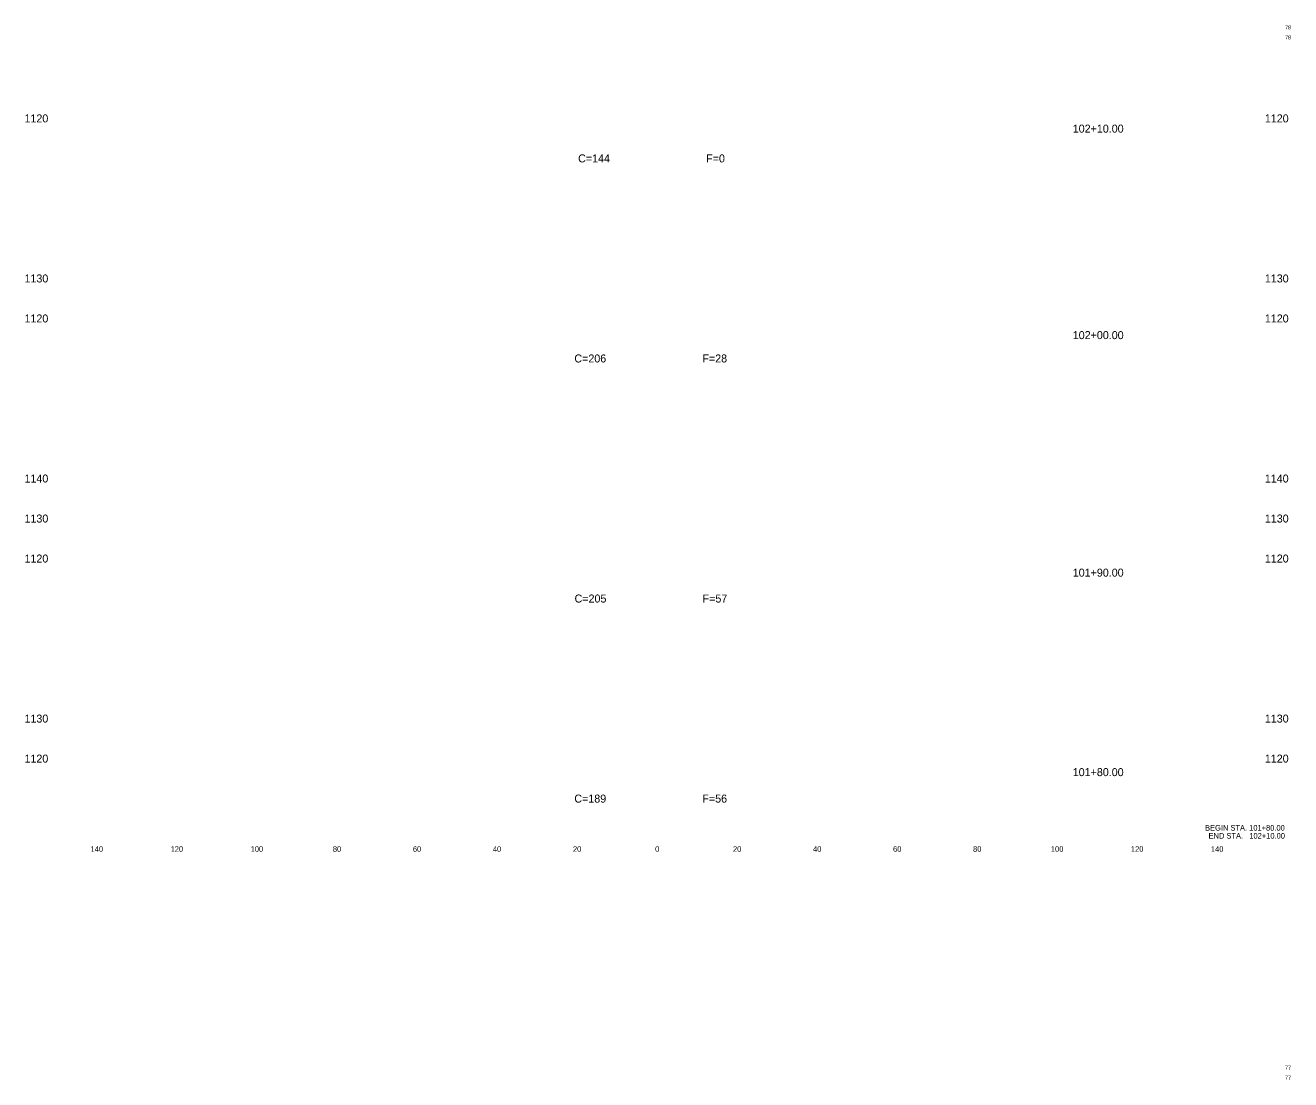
# Model space of a CAD drawing. Extents: x -200 to 1318, y -200 to 2244.
# Drawn here: x 1001.9 to 1318.2, y 1980.8 to 2244.3 of the extents above; entities that cross this region are included whole.
import ezdxf

# ---------------------------------------------------------------- set-up
doc = ezdxf.new("R2010")
doc.units = 0
for name, color, linetype in [('Default', 7, 'Continuous'), ('DESIGN - SHEET - Corner Text', 7, 'Continuous'), ('DESIGN - TYPICAL - Text', 7, 'Continuous')]:
    doc.layers.add(name, color=color, linetype=linetype)

msp = doc.modelspace()

# ---------------------------------------------------------------- texts
at = {"layer": 'Default'}
for s, height, p in [('     1120     ', 2, (998.01, 2220)), ('     1120     ', 2, (1308.01, 2220)), ('     102+10.00     ', 2, (1260, 2217.44)), ('     1130     ', 2, (998.01, 2180)), ('     1130     ', 2, (1308.01, 2180)), ('     1120     ', 2, (998.01, 2170)), ('     1120     ', 2, (1308.01, 2170)), ('     102+00.00     ', 2, (1260, 2165.84)), ('     1140     ', 2, (998.01, 2130)), ('     1140     ', 2, (1308.01, 2130)), ('     1130     ', 2, (998.01, 2120)), ('     1130     ', 2, (1308.01, 2120)), ('     1120     ', 2, (998.01, 2110)), ('     1120     ', 2, (1308.01, 2110)), ('     101+90.00     ', 2, (1260, 2106.47)), ('     1130     ', 2, (998.01, 2070)), ('     1130     ', 2, (1308.01, 2070)), ('     1120     ', 2, (998.01, 2060)), ('     1120     ', 2, (1308.01, 2060)), ('     101+80.00     ', 2, (1260, 2056.62)), ('     140     ', 1.4, (1015.65, 2037.7)), ('     120     ', 1.4, (1035.65, 2037.7)), ('     100     ', 1.4, (1055.65, 2037.7)), ('     80     ', 1.4, (1076.2, 2037.7)), ('     60     ', 1.4, (1096.2, 2037.7)), ('     40     ', 1.4, (1116.2, 2037.7)), ('     20     ', 1.4, (1136.2, 2037.7)), ('     0     ', 1.4, (1156.74, 2037.7)), ('     0     ', 1.4, (1156.74, 2037.7)), ('     20     ', 1.4, (1176.2, 2037.7)), ('     40     ', 1.4, (1196.2, 2037.7)), ('     60     ', 1.4, (1216.2, 2037.7)), ('     80     ', 1.4, (1236.2, 2037.7)), ('     100     ', 1.4, (1255.65, 2037.7)), ('     120     ', 1.4, (1275.65, 2037.7)), ('     140     ', 1.4, (1295.65, 2037.7))]:
    msp.add_text(s, height=height, dxfattribs=at).set_placement(p)
at = {"layer": 'DESIGN - SHEET - Corner Text'}
for s, height, p in [('78', 1, (1316.75, 2243.25)), ('78', 1, (1316.75, 2240.75)), ('BEGIN STA. 101+80.00', 1.4, (1296.78, 2043)), ('END STA.   102+10.00', 1.4, (1297.65, 2041)), ('77', 1, (1316.75, 1983.25)), ('77', 1, (1316.75, 1980.75))]:
    msp.add_text(s, height=height, dxfattribs=at).set_placement(p)
at = {"layer": 'DESIGN - TYPICAL - Text'}
for s, p in [('C=144', (1140.1, 2210)), ('F=0', (1172.1, 2210)), ('C=206', (1139.16, 2160)), ('F=28', (1171.16, 2160)), ('C=205', (1139.21, 2100)), ('F=57', (1171.21, 2100)), ('C=189', (1139.15, 2050)), ('F=56', (1171.15, 2050))]:
    msp.add_text(s, height=2, dxfattribs=at).set_placement(p)

doc.saveas('drawing.dxf')
